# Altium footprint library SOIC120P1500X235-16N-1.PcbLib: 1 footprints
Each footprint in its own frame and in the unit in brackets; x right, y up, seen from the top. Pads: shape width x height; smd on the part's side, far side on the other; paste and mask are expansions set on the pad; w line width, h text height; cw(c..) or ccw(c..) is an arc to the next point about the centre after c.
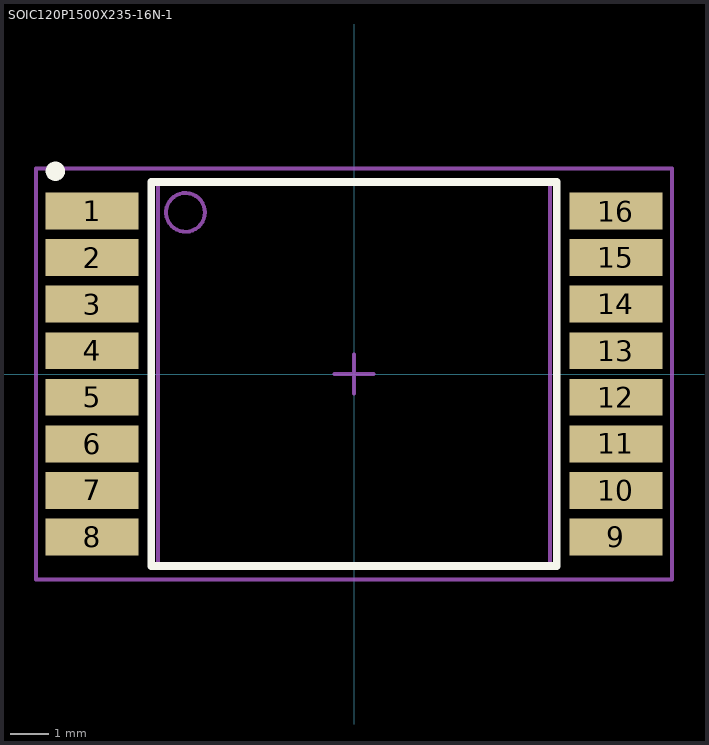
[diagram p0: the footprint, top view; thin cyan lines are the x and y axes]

## SOIC120P1500X235-16N-1 [mm] "SOIC,1.20mm pitch;16 pin,10.15mm W X 9.90mm L X 2.35mm H body"
height 2.35
pads (16):
  rect 2.4x0.95 smd paste+0 mask+0: 1(-6.75,4.2) 2(-6.75,3) 3(-6.75,1.8) 4(-6.75,0.6) 5(-6.75,-0.6) 6(-6.75,-1.8) 7(-6.75,-3) 8(-6.75,-4.2) 9(6.75,-4.2) 10(6.75,-3) 11(6.75,-1.8) 12(6.75,-0.6) 13(6.75,0.6) 14(6.75,1.8) 15(6.75,3) 16(6.75,4.2)
Top Overlay:
  circle w0.25: c-7.696,5.225 r0.125
  lines w0.2: -5.225,-4.95 5.225,-4.95 5.225,4.95 -5.225,4.95 -5.225,-4.95
M3 (ASY_Text_Top):
  text ".DESIGNATOR" at 0,0 h1.2
M13 (CMP_Body_OTL_Top):
  circle w0.1: c-4.343,4.166 r0.5
  lines w0.1: -5.05,-4.95 5.05,-4.95 5.05,4.95 -5.05,4.95 -5.05,-4.95
M15 (CMP_Courtyard_Top):
  lines w0.1: -0.5,0 0.5,0 ; 0,-0.5 0,0.5 ; -8.2,-5.3 -8.2,5.3 8.2,5.3 8.2,-5.3 -8.2,-5.3
3D body "PG-HDSOP-16-1_Z8B00189145_V01_3D.stp": height 2.2, standoff -0.16, extent -7.5,-4.95 7.5,4.95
